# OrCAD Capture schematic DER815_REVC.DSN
size C
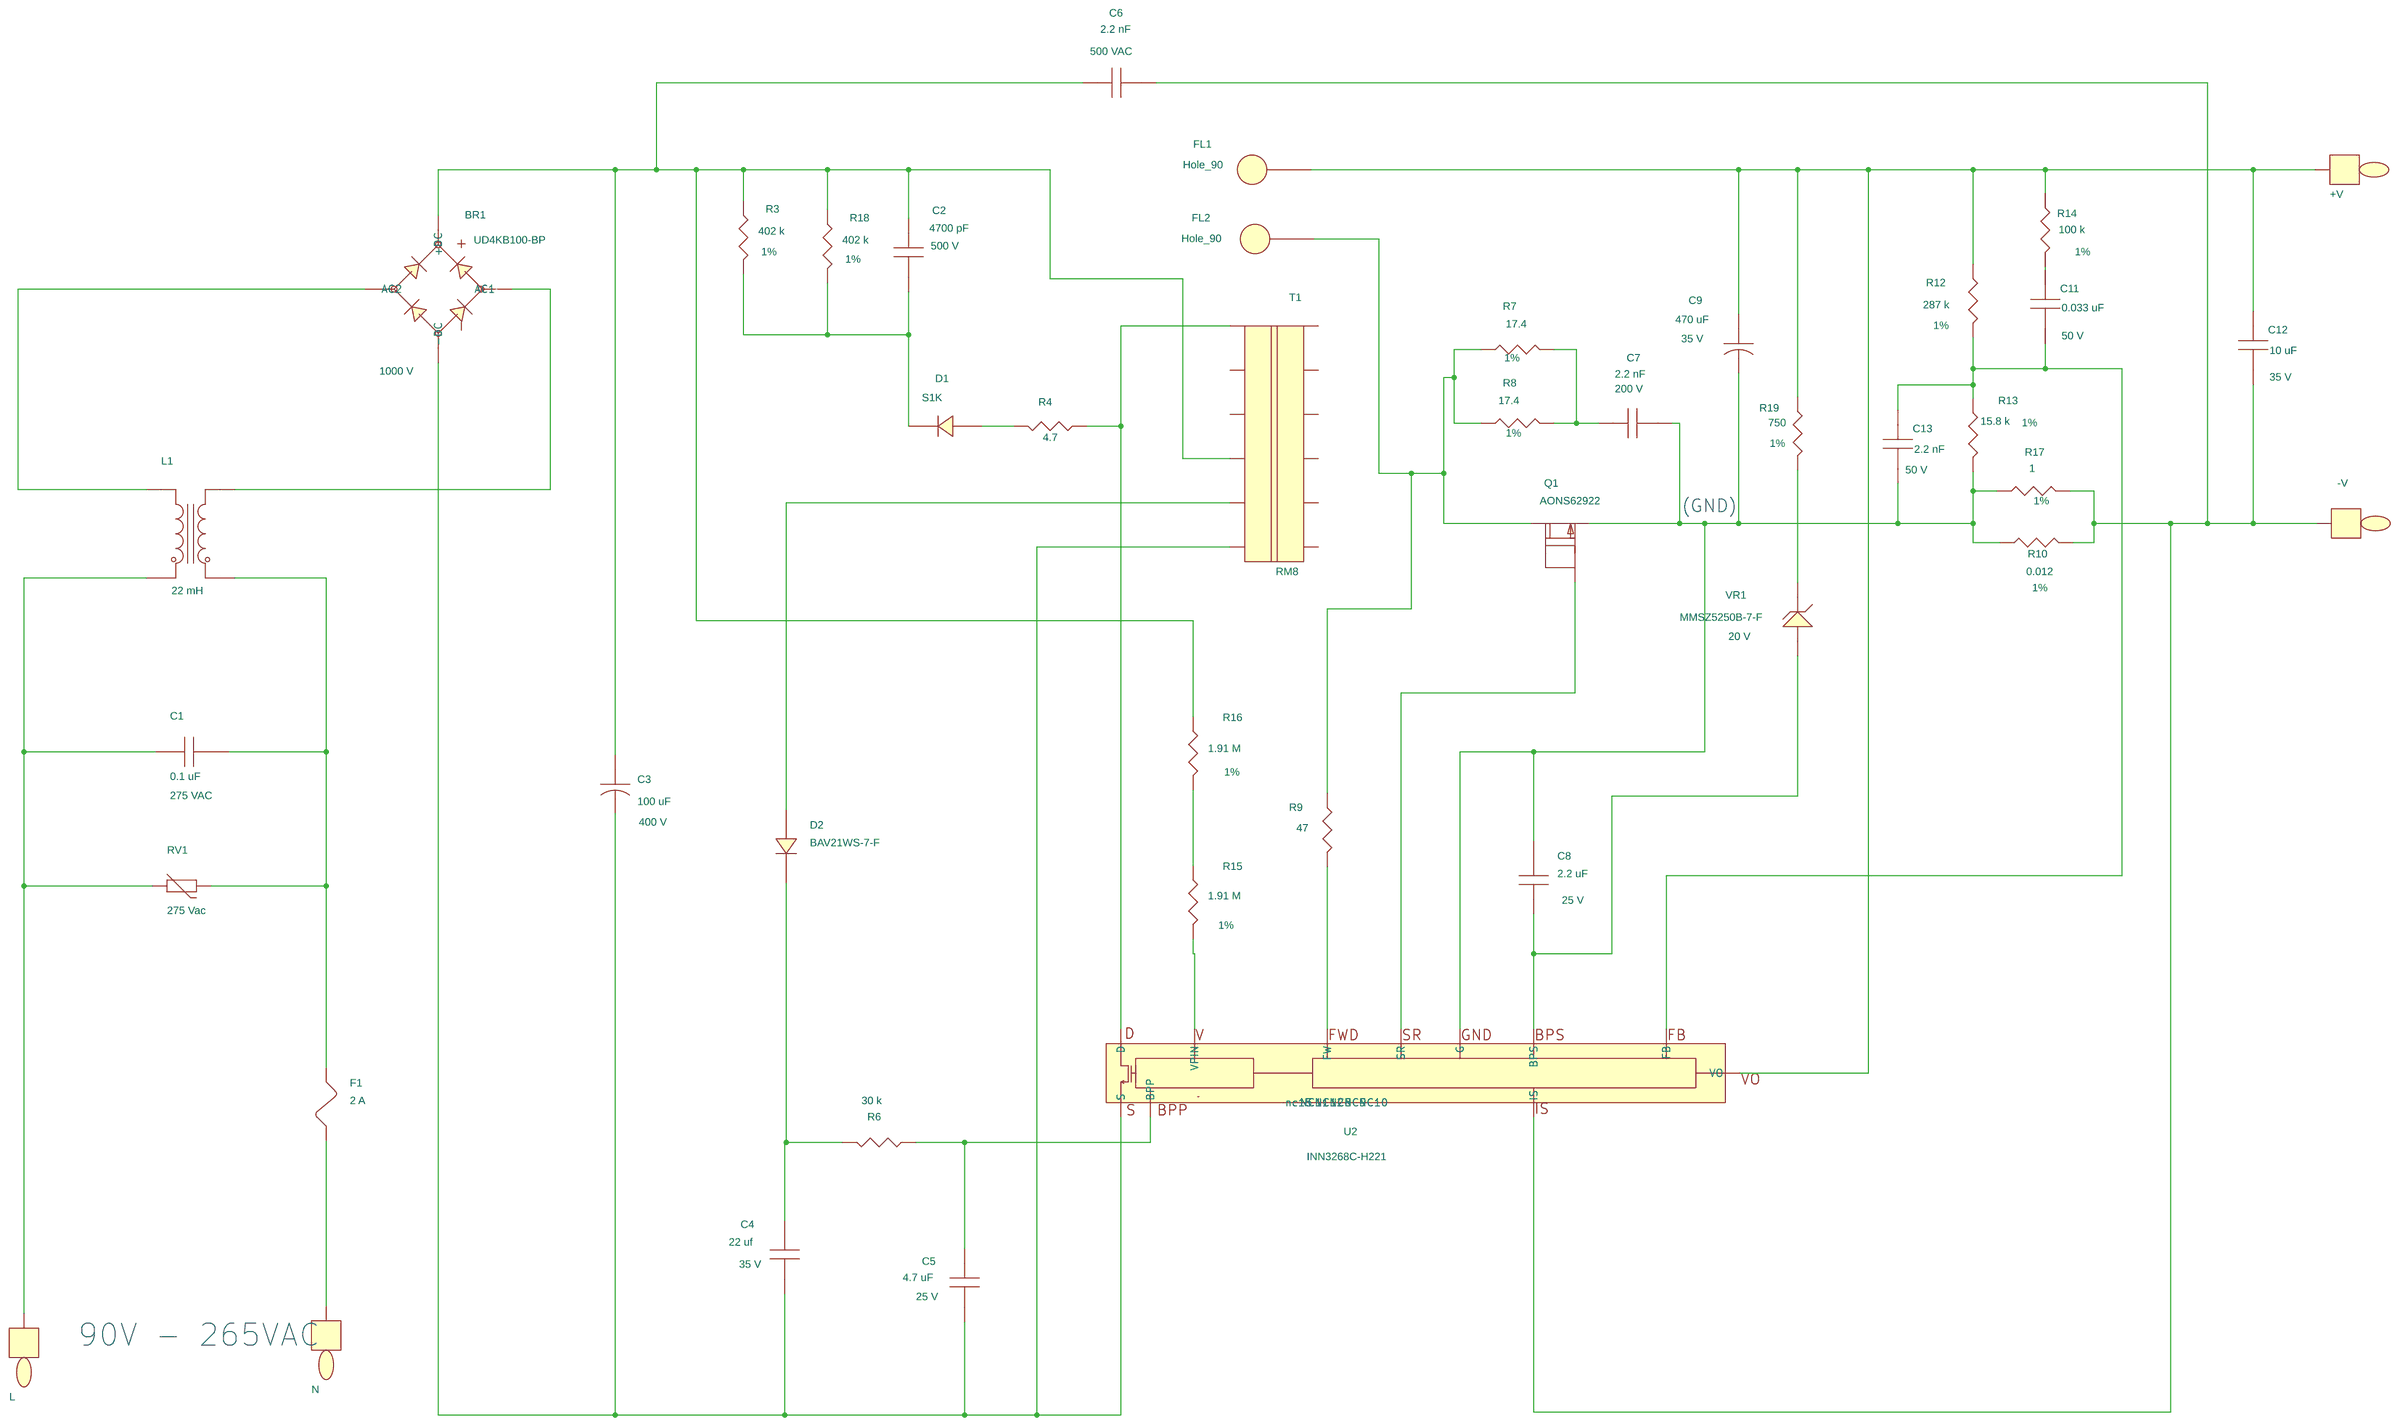
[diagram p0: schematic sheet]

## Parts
BR1  UD4KB100-BP  [pidaxbridgeD3K]
C1  0.1 uF  [pinpxcaprad5x13x11p1mm040]
C2  4700 pF  [pismc0805]
C3  100 uF  [pipolcapclyd630ls300040]
C4  22 uf  [pismc1206]
C5  4.7 uF  [pismc0805]
C6  2.2 nF  [pi_np475x200ls395d040]
C7  2.2 nF  [pismc0805]
C8  2.2 uF  [pismc0805]
C9  470 uF  [pipolcapcyld400ls200040]
C11  0.033 uF  [pismc0603]
C12  10 uF  [pismc0805]
C13  2.2 nF  [pismc0603]
D1  S1K  [pismdo214ac12]
D2  BAV21WS-7-F  [pismsod323]
F1  2 A  [pi_rst_microfuse]
FL1  Hole_90  [pi_hole_70mil]
FL2  Hole_90  [pi_hole_70mil]
L1  22 mH  [pi_ind_4p_21p5x11mmd041]
Q1  AONS62922  [pismpqfn5x6b]
R3  402 k  [pismr1206]
R4  4.7  [pismr1206]
R6  30 k  [pismr0603]
R7  17.4  [pismr1206]
R8  17.4  [pismr1206]
R9  47  [pismr0603]
R10  0.012  [pismr0805]
R12  287 k  [pismr0603]
R13  15.8 k  [pismr0603]
R14  100 k  [pismr0603]
R15  1.91 M  [pismr1206]
R16  1.91 M  [pismr1206]
R17  1  [pismr0603]
R18  402 k  [pismr1206]
R19  750  [pismr0805]
RV1  275 Vac  [pidisc350x160ls210x140040]
T1  RM8  [pi_bobbin_rm8_12p_enertronic]
TP1  L  [pitpkeystone100x100]
TP2  N  [pitpkeystone100x100]
TP10  -V  [pitpkeystone100x100]
TP11  +V  [pitpkeystone100x100]
U2  INN3268C-H221  [pi_ic_insop_24d]
VR1  MMSZ5250B-7-F  [pi_sm_sod-123_12]

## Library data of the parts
BR1 = DISCRETE_BRIDGE_+~~-: ALT_SYMBOLS: pidaxbridgeD3K_horz; Disp_Voltage: 1000 V; FPLIST: pidaxbridgeD3K,pidaxbridgeD3K_horz; Part Number: 15-01213-00
C1 = CAP_NP: ALT_SYMBOLS: pinpxcaprad5x13x11p1mm040h; COMPGROUP: 1; Disp_Voltage: 275 VAC; FPLIST: pinpxcaprad5x13x11p1mm040,pinpxcaprad5x13x11p1mm040h; Part Number: 20-09109-00; Voltage: 275 VAC
C2 = CAP_NP: Disp_Voltage: 500 V; Part Number: 20-09199-00; Voltage: 500 V
C3 = CAP_POL: ALT_SYMBOLS: pipolcapclyd630ls3000401260h; Disp_Voltage: 400 V; FPLIST: pipolcapclyd630ls300040,pipolcapclyd630ls3000401260h; Part Number: 20-09100-00; Voltage: 400 V
C4 = CAP_NP: Disp_Voltage: 35 V; Part Number: 20-01138-00; Voltage: 35 V
C5 = CAP_NP: Disp_Voltage: 25 V; Part Number: 20-09137-00; Voltage: 16 V
C6 = CAP_NP: Disp_Voltage: 500 VAC; Part Number: 20-01062-00; Voltage: 500 VAC
C7 = CAP_NP: Disp_Voltage: 200 V; PCB Editor PCBFP: pismc0603; Part Number: 20-00761-00; Voltage: 200 V
C8 = CAP_NP: Disp_Voltage: 25 V; Part Number: 20-08603-00; Voltage: 25 V
C9 = CAP_POL: ALT_SYMBOLS: pipolcapcyld400ls200040800h; COMPGROUP: 3; Disp_Voltage: 35 V; FPLIST: pipolcapcyld400ls200040,pipolcapcyld400ls200040800h; Part Number: 20-00048-00; Voltage: 35 V
C11 = CAP_NP: ALT_SYMBOLS: pismc0603_1; Disp_Voltage: 50 V; FPLIST: pismc0603,pismc0603_1; Part Number: 20-09224-00; Voltage: 50 V
C12 = CAP_NP: ALT_SYMBOLS: pismc0805_1; Disp_Voltage: 35 V; FPLIST: pismc0805,pismc0805_1; Part Number: 20-08720-00; Voltage: 35 V
C13 = CAP_NP: Disp_Voltage: 50 V; Part Number: 20-08677-00; Voltage: 50 V
D1 = DIODE: Part Number: 15-01296-00
D2 = DIODE: COMPGROUP: 1; Part Number: 15-00385-00
F1 = FUSE: ALT_SYMBOLS: pirstmicrofusehoz; FPLIST: pi_rst_microfuse,pirstmicrofusehoz; Part Number: 40-00021-00
FL1 FL2 = FlyingLead: Part Number: 35-00282-00
L1 = INDUCTOR_4P_revB: Part Number: 30-00487-00
Q1 = FET_N_SGD_123_4_5678: Part Number: 50-00275-00
R3 R18 = R: Disp_Tol: 1%; Part Number: 05-00443-00
R4 = R: Part Number: 05-01296-00
R6 = R: Part Number: 05-01723-00
R7 R8 = R: Disp_Tol: 1%; Part Number: 05-00024-00
R9 = R: Part Number: 05-01656-00
R10 = R: Disp_Tol: 1%; Part Number: 05-06519-00
R12 = R: Disp_Tol: 1%; Part Number: 05-01218-00
R13 = R: Disp_Tol: 1%; Part Number: 05-03201-00
R14 = R: Disp_Tol: 1%; Part Number: 05-01174-00
R15 R16 = R: Disp_Tol: 1%; Part Number: 05-05409-00
R17 = R: Disp_Tol: 1%; Part Number: 05-01270-00
R19 = R: Disp_Tol: 1%; Part Number: 05-00672-00
RV1 = VARISTOR: ALT_SYMBOLS: pi_disc_354x220_ls220x10_040_h; FPLIST: pidisc350x160ls210x140040,pi_disc_354x220_ls220x10_040_h; Part Number: 85-00015-00
T1 = BRM8_12P_GENERIC_1: ALT_SYMBOLS: pi_bobbin_rm8_12p_clp; FPLIST: pi_bobbin_rm8_12p_enertronic,pi_bobbin_rm8_12p_clp; Part Number: 25-01084-00
TP1 TP10 = TESTPOINT: Part Number: 35-00079-00
TP2 = TESTPOINT: Part Number: 35-00081-00
TP11 = TESTPOINT: Part Number: 35-00080-00
U2 = Inno3CP: Part Number: 10-01044-02
VR1 = DIODE_ZENER: Disp_Voltage: 20 V; Part Number: 15-01325-00

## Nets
NC8: U2.8(NC8)
NC9: U2.9(NC9)
NC10: U2.10(NC10)
NC11: U2.11(NC11)
NC12: U2.12(NC12)
NC15: U2.15(nc15)
N11266868: BR1.1(+DC) C2.1 C3.1 C6.1 R3.1 R16.1 R18.1 T1.10
N11266916: C9.1 C12.1 FL1.1 R12.1 R14.1 R19.2 TP11.1 U2.6(VO)
N11267038: C2.2 D1.1 R3.2 R18.2
N11267062: C11.1 R14.2
N11267102: FL2.1 Q1.5(D) R7.2 R8.2 R9.1
N11267110: C7.1 R7.1 R8.1
N11267188: C11.2 C13.1 R12.2 R13.1 U2.3(FB)
N11267230: C6.2 C12.2 R10.2 R17.2 TP10.1 U2.1(IS)
N11267290: C7.2 C8.2 C9.2 C13.2 Q1.1(S) R10.1 R13.2 R17.1 U2.2(G)
N11267634: BR1.2(AC1) L1.4
N11267730: BR1.4(-DC) C3.2 C4.2 C5.2 T1.12 U2.16(S)
N11267828: C1.2 F1.2 L1.3 RV1.2
N11267852: R9.2 U2.7(FW)
N11267958: C8.1 U2.4(BPS) VR1.2
N11268086: C5.1 R6.2 U2.14(BPP)
N11268620: F1.1 TP2.1
N11268626: C1.1 L1.1 RV1.1 TP1.1
N11270541: BR1.3(AC2) L1.2
N11272042: R4.2 T1.1 U2.24(D)
N11272779: D2.2 T1.11
N11273620: C4.1 D2.1 R6.1
N11285778: Q1.4(G) U2.5(SR)
N11293604: R15.1 R16.2
N11293623: R15.2 U2.13(VPIN)
N11314206: D1.2 R4.1
N11323484: R19.1 VR1.1

Not connected (* = marked no-connect by the designer): Q1 2(S2) 3(S3) 6(D6) 7(D7) 8(D8); T1 2 3 4 5 6 7 8 9

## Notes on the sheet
- (GND)
- 90V - 265VAC
